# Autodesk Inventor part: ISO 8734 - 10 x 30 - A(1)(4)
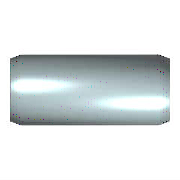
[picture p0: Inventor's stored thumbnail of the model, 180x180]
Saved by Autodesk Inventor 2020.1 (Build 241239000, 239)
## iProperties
Created: 2019-01
Part Number: ISO 8734 - 10 x 30 - A(1)(4)
Material: Stahl
Description: Zylinderstifte aus gehärtetem Martensit-Edelstahl (Passstifte)
Document SubType Name: Modeling
Standard: ISO 8734
Designer: lutzd
Standard Revision: Second edition 1997-11-15
Standards Organization: ISO
Language: de-DE
Size Designation: 10 x 30 - A
Categories: <MemberInstance><Categories><Category DisplayName="Verbindungselemente" InternalName="e4da775c-781d-43d5-af7c-5136215cf5a6" Mnemonic="FSTN"><Category DisplayNam
Mass: 18.2412 g
Surface Area: 10.6515 cm^2
Volume: 2.32373 cm^3
Density: 7.85 g/cm^3
Appearance: Plate
IsCustomPart: 0
Author: lutzd
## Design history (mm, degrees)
sketch "Skizze"
  geometry: C1 r 5 at (0, 0); 1 further point
  constraints: 1 centre point, 1 coincident
  dimensions: "d1" = 10 diameter of C1 (= NND)
extrude "Körper" new body sketch "Skizze" distance "d2" = 30 (= NLG); taper "d3" = 0 deg
chamfer "Skizze2" distance "d8" = 2 (= PHH); stored, may be unused: angle "d9" = 15 deg (= FAWI), second distance "d12" = 2 (= PHH)
body "Solid1"
chamfer "Fase1" distance "d4" = 2 (= PHH); stored, may be unused: angle "d5" = 15 deg (= FAWI), second distance "d11" = 2 (= PHH)
other parameters: "NND" = 10 [user parameter; used in 1 equation term], "NLG" = 30 [user parameter; used in 1 equation term], "PHH" = 2 [user parameter; used in 5 equation terms], "FAWI" = 15 deg [user parameter; used in 2 equation terms], "d13" = 0, "d15" = 0, "d16" = 0, "PHH2" = 2 (= PHH) [user parameter], "FAWI2" = 15 deg [user parameter]
